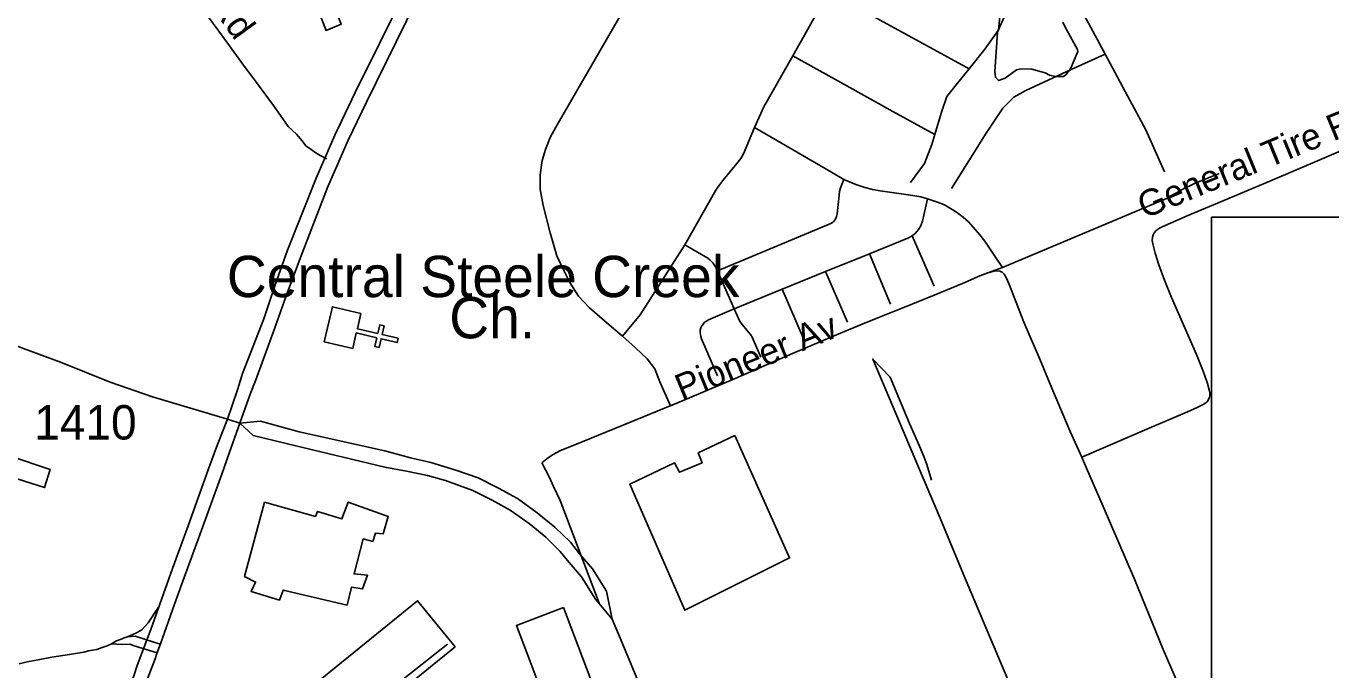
# Model space of a CAD drawing. Extents: x 1383679 to 1536984, y 460658 to 651027.
# Drawn here: x 1418729 to 1423468, y 506884 to 509221 of the extents above; entities that cross this region are included whole.
import ezdxf

# ---------------------------------------------------------------- set-up
doc = ezdxf.new("R2010")
doc.units = 0
for name, color, linetype in [('Exist Cultural Church CELL', 7, 'Continuous'), ('Exist Cultural Church Label', 7, 'Continuous'), ('Exist Cultural Warehouse Building Footprint', 7, 'Continuous'), ('Exist Hydrographic Misc Water Feature', 7, 'Continuous'), ('Exist Railroad Spur', 7, 'Continuous'), ('Exist Road Non-System Type 51', 7, 'Continuous'), ('Exist Road Non-System Type 51 Label', 7, 'Continuous'), ('Exist Road Primary NC Divided Attributed', 7, 'Continuous'), ('Exist Road Primary NC UnDivided 4 Lane Attributed', 7, 'Continuous'), ('Exist Road Secondary Type 51 Attributed', 7, 'Continuous'), ('Exist Road Secondary Type 51 Divided Attributed', 7, 'Continuous'), ('Exist Road Secondary Type 51 Number Label', 7, 'Continuous'), ('Map Preparation Inset Cut Line', 7, 'Continuous')]:
    doc.layers.add(name, color=color, linetype=linetype)

msp = doc.modelspace()

# ---------------------------------------------------------------- linework, layer by layer
at = {"layer": 'Exist Cultural Church CELL'}
msp.add_lwpolyline([(1419944.9, 508178.1), (1419932, 508122.6), (1420006.1, 508105.2), (1420013.4, 508136.4), (1420029, 508132.8), (1420021.7, 508101.6), (1420080.2, 508087.9), (1420076.6, 508072.3), (1420018, 508086), (1420010.7, 508054.8), (1419995.2, 508058.5), (1420002.5, 508089.6), (1419928.3, 508107), (1419915.1, 508050.9), (1419811.4, 508075.2), (1419841.2, 508202.3)], close=True, dxfattribs=at)
at = {"layer": 'Exist Cultural Warehouse Building Footprint'}
for points in [[(1419776.4, 509673.2), (1419749.5, 509617.6), (1419727.3, 509627.8), (1419709.8, 509605.1), (1419732, 509588.1), (1419710.9, 509539.3), (1419760.1, 509513.2), (1419729.7, 509440.6), (1419788.1, 509408.9), (1419760.1, 509354.4), (1419818.5, 509205.8), (1419873.5, 509228.5), (1419825.5, 509348.7), (1419946, 509590.4), (1419939, 509594.9), (1419965.8, 509651.6), (1419976.4, 509647.1), (1419998.6, 509694.7), (1419898, 509745.8), (1419874.6, 509698.1), (1419898, 509678.8), (1419874.6, 509627.8), (1419776.4, 509673.2)], [(1421303.5, 507735.2), (1421170.2, 507671.6), (1421184.2, 507635.3), (1421102.4, 507601.3), (1421083.7, 507635.3), (1420922.3, 507558.2), (1421121.1, 507099.9), (1421502.3, 507290.5), (1421303.5, 507735.2)], [(1418650.4, 507592.2), (1418795.4, 507545.7), (1418816.4, 507611), (1418672, 507660.3)], [(1419595.2, 507493), (1419522.7, 507223), (1419562.4, 507202.6), (1419546.1, 507168.6), (1419649, 507136.8), (1419663, 507173.1), (1419894.5, 507118.7), (1419910.9, 507184.4), (1419950.6, 507177.6), (1419969.4, 507227.5), (1419920.2, 507232.1), (1419953, 507359.1), (1419988.1, 507350.1), (1419997.4, 507379.5), (1420025.5, 507377.3), (1420044.2, 507440.8), (1419899.2, 507493), (1419875.8, 507431.7), (1419786.9, 507459), (1419779.9, 507440.8), (1419595.2, 507493)], [(1420287.4, 506966.7), (1420151.1, 507134.8), (1419373, 506503.8), (1419509.3, 506335.7), (1420287.4, 506966.7)], [(1420680.3, 507109.6), (1420509.6, 507044.5), (1420633.5, 506719.4), (1420804.2, 506784.4), (1420680.3, 507109.6)]]:
    msp.add_lwpolyline(points, dxfattribs=at)
at = {"layer": 'Exist Hydrographic Misc Water Feature'}
msp.add_lwpolyline([(1422494.1, 509235.9), (1422501.6, 509220.1), (1422547.7, 509137.1), (1422549.5, 509129), (1422522.2, 509065.7), (1422505.8, 509044.1), (1422497.6, 509038.3), (1422469.6, 509038.9), (1422445.7, 509043.4), (1422429.9, 509051.8), (1422382.1, 509064.9), (1422342.1, 509065.7), (1422326, 509062.1), (1422285.4, 509033), (1422261.2, 509023.6), (1422249.5, 509035.9), (1422247.9, 509055.9), (1422257, 509199.6), (1422261.2, 509207.5), (1422266.3, 509255.4)], dxfattribs=at)
at = {"layer": 'Exist Railroad Spur'}
for points in [[(1422017.2, 507573.1), (1422000.2, 507629.4), (1421990, 507658.8), (1421974.2, 507695.6), (1421938.2, 507778.2), (1421867, 507946.2), (1421804.4, 508012.2), (1421878.7, 507837.1), (1421970, 507619.3), (1422048.6, 507435.1), (1422133.7, 507230.1), (1422205, 507060.2), (1422267.7, 506911.8), (1422324.7, 506777)], [(1420259.1, 506977.4), (1420098, 506849.4), (1420075, 506831), (1419908.8, 506698.6), (1419782.2, 506599.3), (1419609.3, 506462.2), (1419500, 506375.8), (1419484.5, 506360.7), (1419468.9, 506343.9), (1419451.5, 506325.6), (1419435.8, 506307.7), (1419417.7, 506284.4), (1419398.2, 506260.3), (1419379.9, 506235.2), (1419359.5, 506211), (1419331.5, 506179.2), (1419311.1, 506153.2)]]:
    msp.add_lwpolyline(points, dxfattribs=at)
at = {"layer": 'Exist Road Non-System Type 51'}
for p, q in [((1422154, 509066.3), (1421643.5, 509346.2)), ((1422027.9, 508276.7), (1421947.1, 508460.3)), ((1421791.8, 508394.5), (1421633.1, 508329.8)), ((1421868.5, 508211.2), (1421791.8, 508394.5)), ((1421301.1, 508194.5), (1421240.2, 508333.2)), ((1421633.1, 508329.8), (1421475.5, 508265.6)), ((1421712.4, 508146.2), (1421633.1, 508329.8)), ((1421475.5, 508265.6), (1421301.1, 508194.5)), ((1421554.6, 508081), (1421475.5, 508265.6))]:
    msp.add_line(p, q, dxfattribs=at)
for points in [[(1421358.4, 510032.8), (1421311.9, 509977.7), (1421262.6, 509912), (1421203.6, 509818.4), (1421146.1, 509723.2), (1421027.9, 509504.9), (1420653.6, 508854.8), (1420632.9, 508817), (1420615.4, 508773.6), (1420603.2, 508733.5), (1420596.4, 508681.3), (1420596.4, 508629.2), (1420606.8, 508570), (1420632.9, 508470.9), (1420657.1, 508387.4), (1420681.6, 508333.5), (1420704.1, 508290), (1420735.5, 508241.2), (1420775.5, 508197.8), (1420838.1, 508143.8), (1420895.6, 508095.1)], [(1419038.4, 509773.5), (1419039.7, 509762.8), (1419041.1, 509753.4), (1419043.5, 509744.4), (1419046.6, 509735.7), (1419050.8, 509727), (1419068.4, 509698.3), (1419101.4, 509651.1), (1419179.3, 509545.1), (1419272.1, 509418), (1419351.7, 509307.8), (1419438.4, 509189.4), (1419528.7, 509066), (1419541.4, 509049.1), (1419627.5, 508933.3), (1419680.6, 508857.4), (1419710.8, 508829.3), (1419731.6, 508804.4), (1419745.5, 508786.5), (1419763.8, 508773.9), (1419777.2, 508763.2), (1419797.3, 508751.2), (1419820.7, 508739.6)], [(1421643.5, 509346.2), (1421567, 509207.5), (1421513.9, 509113.7)], [(1422300.8, 509297.2), (1422259.9, 509205.9), (1422210.8, 509137.2), (1422154, 509066.3)], [(1422648.4, 509119.8), (1422619.2, 509174.4), (1422557.5, 509288.2)], [(1421513.9, 509113.7), (1421409.1, 508928.6), (1421374.1, 508852.8)], [(1422030.1, 508828.1), (1421877.1, 508911.5), (1421710.2, 509004.8), (1421513.9, 509113.7)], [(1422648.4, 509119.8), (1422524.8, 509063.6), (1422360.4, 508987.6), (1422316.2, 508963), (1422277, 508923.8), (1422215.6, 508833), (1422090.1, 508631.2)], [(1422864.1, 508692.2), (1422796.6, 508844.6), (1422721.4, 508983.4), (1422648.4, 509119.8)], [(1422154, 509066.3), (1422112.6, 509014.6), (1422073.4, 508965.5), (1422053.8, 508909.1), (1422030.1, 508828.1)], [(1421374.1, 508852.8), (1421334.9, 508757.8), (1421324.5, 508741), (1421310.9, 508722.2), (1421259.9, 508660.7), (1421245.5, 508640.9), (1421234.5, 508625.2), (1421121.8, 508426.9)], [(1421699.4, 508664.3), (1421653.9, 508691.2), (1421374.1, 508852.8)], [(1422030.1, 508828.1), (1422019.4, 508791.3), (1421992.4, 508722.6), (1421941.4, 508653)], [(1422563.6, 507656.1), (1422807.7, 507760.8), (1422947.2, 507821.3), (1422982.9, 507836.8), (1423007.1, 507848.9), (1423015, 507854.1), (1423018.6, 507857.5), (1423024.3, 507865.5), (1423027.7, 507873.7), (1423028.8, 507880.2), (1423028.6, 507889.3), (1423026.3, 507900.6), (1423020.1, 507923), (1423009, 507955), (1423001.6, 507974.5), (1422979.9, 508029.4), (1422889.9, 508236.1), (1422864.2, 508298.7), (1422843.3, 508355), (1422829.7, 508397.4), (1422821.2, 508430.4), (1422819.6, 508443.2), (1422820.5, 508455.4), (1422822.8, 508463.4), (1422827, 508470.5), (1422832.7, 508477.8), (1422838.3, 508482.8), (1422845.7, 508487.7), (1422855.7, 508492.8), (1422946.8, 508532.5), (1423093.5, 508593.8), (1423254.8, 508662.3), (1423427.7, 508735.8), (1423609.2, 508813.4)], [(1421699.4, 508664.3), (1421687.2, 508634.7), (1421683.6, 508621), (1421682, 508607.3), (1421675.1, 508539.6), (1421672.5, 508530.2), (1421668.9, 508520.7), (1421661.5, 508511.2), (1421651.5, 508504.9), (1421240.2, 508333.2)], [(1422003.4, 508594.1), (1421978.5, 508601.3), (1421949.6, 508606.5), (1421830.6, 508623), (1421802.8, 508628.2), (1421775.9, 508635.4), (1421742.9, 508646.8), (1421699.4, 508664.3)], [(1423062.2, 508686.1), (1422973.1, 508649.9), (1422953.6, 508640.8), (1422936.9, 508633.1), (1422916.2, 508621.4), (1422889.1, 508605.9), (1422871, 508595.6), (1422275.4, 508344.9)], [(1422003.4, 508594.1), (1421984.8, 508513.4), (1421979.1, 508496.5), (1421970.5, 508483.2), (1421959.4, 508469.7), (1421947.1, 508460.3)], [(1422275.4, 508344.9), (1422249.9, 508382), (1422231.1, 508411.1), (1422211.8, 508440.2), (1422193.1, 508463.7), (1422168.9, 508491.3), (1422151.6, 508510.8), (1422132.1, 508528), (1422108.6, 508545.3), (1422087.2, 508559.2), (1422064.4, 508572.3), (1422039.5, 508582.7), (1422003.4, 508594.1)], [(1421121.8, 508426.9), (1420959.2, 508173.3), (1420895.6, 508095.1)], [(1421240.2, 508333.2), (1421232.8, 508347.6), (1421223.2, 508361.4), (1421213.8, 508371.4), (1421204.6, 508378.5), (1421121.8, 508426.9)], [(1421947.1, 508460.3), (1421946.9, 508460.2), (1421931.2, 508451.1), (1421791.8, 508394.5)], [(1422563.6, 507656.1), (1422521.6, 507749.6), (1422455.2, 507907.2), (1422411.2, 508012.3), (1422353.5, 508146), (1422301.2, 508280.3), (1422290.5, 508306.4), (1422282.1, 508321.1), (1422274.8, 508328.1), (1422266.4, 508331.6), (1422258, 508332.7), (1422245.8, 508331.3), (1422222.5, 508325.4), (1422192.9, 508314.5), (1422129.9, 508287.3), (1422027.3, 508244.6), (1421949.5, 508212.7), (1421889.6, 508188.6), (1421822.8, 508162.2), (1421765.2, 508139.2), (1421672.5, 508100), (1421512.4, 508032.9), (1421304.9, 507942), (1421115.3, 507861.5), (1420927.1, 507784), (1420748.1, 507711.6), (1420667.1, 507679), (1420643.9, 507666), (1420626.3, 507654.7), (1420601.8, 507635.3)], [(1422275.4, 508344.9), (1422222.5, 508325.4), (1422192.9, 508314.5), (1422130, 508287.3), (1422027.2, 508244.6), (1421949.5, 508212.7), (1421889.6, 508188.6), (1421822.8, 508162.2), (1421765.2, 508139.2), (1421672.5, 508100), (1421512.4, 508032.9), (1421304.9, 507942), (1421115.4, 507861.5), (1421069.9, 507842.8)], [(1421301.1, 508194.5), (1421208, 508154.3), (1421199.9, 508150.4), (1421193.6, 508145.8), (1421187.8, 508139.5), (1421183.1, 508133.2), (1421179.6, 508125.4), (1421177.6, 508117.7), (1421177.2, 508109.1), (1421178, 508101.7), (1421179.6, 508094.2), (1421182.2, 508086.4), (1421240, 507951.8)], [(1421397.9, 508019.1), (1421366.4, 508091.6), (1421360, 508101.5), (1421351.1, 508111.5), (1421325.9, 508142.5), (1421320.6, 508151.4), (1421316.4, 508159.3), (1421301.1, 508194.5)], [(1420895.6, 508095.1), (1420942.5, 508053.4), (1420984.2, 508013.4), (1421012.1, 507976.9), (1421031.1, 507929.9), (1421069.9, 507842.8)], [(1420601.8, 507635.3), (1420629.3, 507584.8), (1420644.7, 507550), (1420668.7, 507498.5), (1420810.8, 507126.4)], [(1423477.8, 505523.3), (1423371.5, 505776), (1423266.7, 506022.1), (1423213.3, 506150.5), (1423150.1, 506292.6), (1423115.3, 506367.2), (1423052.3, 506516.1), (1422954.8, 506737.5), (1422859.6, 506958.1), (1422754.6, 507212.6), (1422641, 507476.7), (1422580.4, 507616.2), (1422566.3, 507650.1), (1422563.6, 507656.1)], [(1419210.2, 507111), (1419172.1, 507054.1), (1419149.8, 507029), (1419129.7, 507018.2), (1419097.5, 507003.8)], [(1419097.5, 507003.8), (1419084.9, 507000), (1419078.3, 506996.4), (1419057.4, 506989.3), (1419038.6, 506978)], [(1419097.5, 507003.8), (1419124.7, 507006), (1419215.9, 506977)], [(1419038.6, 506978), (1419022.8, 506971.5), (1419004.9, 506964.8), (1418985.5, 506957.9), (1418970.5, 506955), (1418957, 506953.1), (1418938, 506948.5), (1418886.8, 506939.6), (1418821.7, 506929.7), (1418772.1, 506920.1), (1418732.1, 506912.4), (1418703.3, 506905.3)], [(1419204.6, 506945.4), (1419121.9, 506971.5), (1419106.1, 506977.3), (1419077.4, 506975.8), (1419038.6, 506978)]]:
    msp.add_lwpolyline(points, dxfattribs=at)
at = {"layer": 'Exist Road Primary NC Divided Attributed'}
for points in [[(1419459.9, 507793.5), (1419496.3, 507900.7), (1419515.4, 507959.7), (1419592.2, 508159), (1419632, 508278.5), (1419678.8, 508407.7), (1419781.9, 508669.8), (1419850.8, 508824.9), (1419923.7, 508980), (1420101.4, 509337.2), (1420198.6, 509533.9), (1420244, 509620.9), (1420306.1, 509730.1), (1420368.2, 509834.4), (1420467.6, 509990), (1420547, 510104), (1420611.8, 510192.1), (1420751.7, 510370.4), (1420877.6, 510513.6), (1420973.8, 510617.5), (1421120.1, 510763.9), (1421400.7, 511026), (1422531.5, 512049.9)], [(1419505.3, 507780.1), (1419543.1, 507884.4), (1419562.9, 507937), (1419632, 508125.6), (1419673.6, 508241.8), (1419725.2, 508381.7), (1419823.5, 508635.2), (1419898.9, 508807), (1419965.8, 508944.8), (1420146.8, 509314.5)]]:
    msp.add_lwpolyline(points, dxfattribs=at)
at = {"layer": 'Exist Road Primary NC UnDivided 4 Lane Attributed'}
for points in [[(1418693.2, 506012), (1418735.9, 506074.2), (1418794, 506163.2), (1418837, 506230.7), (1418880.8, 506308.2), (1418918.8, 506381.5), (1418947.5, 506437.5), (1418978.4, 506502.8), (1419000.6, 506553.7), (1419037.9, 506642.8), (1419065.2, 506713.1), (1419108.9, 506828), (1419132.6, 506899), (1419165.6, 506989.5), (1419181.4, 507030.4), (1419260.7, 507252.2), (1419317, 507406.9), (1419391.4, 507613.3), (1419423.5, 507702.4), (1419459.9, 507793.5)], [(1418723.5, 505967.4), (1418767.2, 506030.6), (1418830.6, 506123), (1418862.8, 506173.3), (1418910.2, 506257.3), (1418942.9, 506317.5), (1418971.9, 506370.7), (1419014, 506452.7), (1419030.6, 506498.3), (1419068.8, 506583.2), (1419103, 506667.4), (1419144.6, 506778.5), (1419171.4, 506855.2), (1419197.2, 506923.4), (1419203.6, 506942.8), (1419216.6, 506978.7), (1419267.9, 507122.1), (1419307.9, 507232.8), (1419355.8, 507364.1), (1419439.5, 507594.9), (1419466.7, 507670.2), (1419505.3, 507780.1)]]:
    msp.add_lwpolyline(points, dxfattribs=at)
at = {"layer": 'Exist Road Secondary Type 51 Attributed'}
for points in [[(1418686.8, 508063.4), (1418853.2, 508000.7), (1419034.7, 507928.5), (1419188.2, 507874.8), (1419459.9, 507793.5)], [(1419459.9, 507793.5), (1419505.3, 507780.1)], [(1420965, 506810.3), (1420893.9, 506981.4), (1420857.6, 507067.6)]]:
    msp.add_lwpolyline(points, dxfattribs=at)
at = {"layer": 'Exist Road Secondary Type 51 Divided Attributed'}
for points in [[(1420857.6, 507067.6), (1420836.6, 507169.3), (1420786.6, 507250.7), (1420739.5, 507305.6), (1420705.7, 507347.3), (1420649.6, 507402), (1420585.5, 507454.4), (1420513.2, 507505.6), (1420445, 507543.7), (1420371.4, 507580.5), (1420290, 507609.4), (1420199.5, 507636.6), (1420124.8, 507653.8), (1420032.4, 507678.8), (1419720.3, 507747.5), (1419580.6, 507786.7), (1419505.3, 507780.1)], [(1419505.3, 507780.1), (1419554.2, 507735), (1419709, 507697.5), (1420032.4, 507620.1), (1420111.1, 507605.1), (1420187.3, 507588.9), (1420252.5, 507571)], [(1420252.5, 507571), (1420352.1, 507535.2), (1420422, 507500.2), (1420486.9, 507464), (1420555.6, 507415.2), (1420616.8, 507365.3), (1420669.2, 507314.1), (1420701.7, 507274.1), (1420746.7, 507221.6), (1420796.6, 507140.5), (1420857.6, 507067.6)]]:
    msp.add_lwpolyline(points, dxfattribs=at)
at = {"layer": 'Map Preparation Inset Cut Line'}
msp.add_lwpolyline([(1423034.8, 508527.4), (1433242.6, 508527.4), (1433242.6, 499593.9), (1423034.8, 499593.9)], close=True, dxfattribs=at)

# ---------------------------------------------------------------- texts
at = {"layer": 'Exist Cultural Church Label'}
for s, p in [('Central Steele Creek', (1419458.1, 508237.3)), ('Ch.', (1420265.8, 508087.7))]:
    msp.add_text(s, height=150, dxfattribs=at).set_placement(p)
at = {"layer": 'Exist Road Non-System Type 51 Label'}
for s, rotation, p in [('Township Rd', 305.9809, (1419054.4, 509765.1)), ('General Tire Rubber Dr', 22.3068, (1422791, 508521)), ('Pioneer Av', 22.3235, (1421111, 507860.3))]:
    msp.add_text(s, height=95, rotation=rotation, dxfattribs=at).set_placement(p)
at = {"layer": 'Exist Road Secondary Type 51 Number Label'}
msp.add_text('1410', height=125, dxfattribs=at).set_placement((1418758.4, 507720.1))

doc.saveas('drawing.dxf')
